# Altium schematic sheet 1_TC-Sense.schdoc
size 307 x 218 mm; Symbol: Drawing-Symbol_A4; Device: Drawing-Symbol_A4; @Project Name: Temp_Con_V116; @Page Count: 2; @Update Date: 2025-01-28; @Create Date: 2025-01-28; @Schematic Name: TC_485; @Page No: 1; @Page Name: TC-Sense; Company: EasyEDA.com; Version: V1.0; Page Size: A4; @Create Time: 02:07:35; @Update Time: 11:24:21; Width: 1170; Height: 825; Region Start: 1; X Region Count: 6; Y Region Count: 4; Blade Width: 10; Title Block Position: 3; @Board Name: TEMP_TC_485
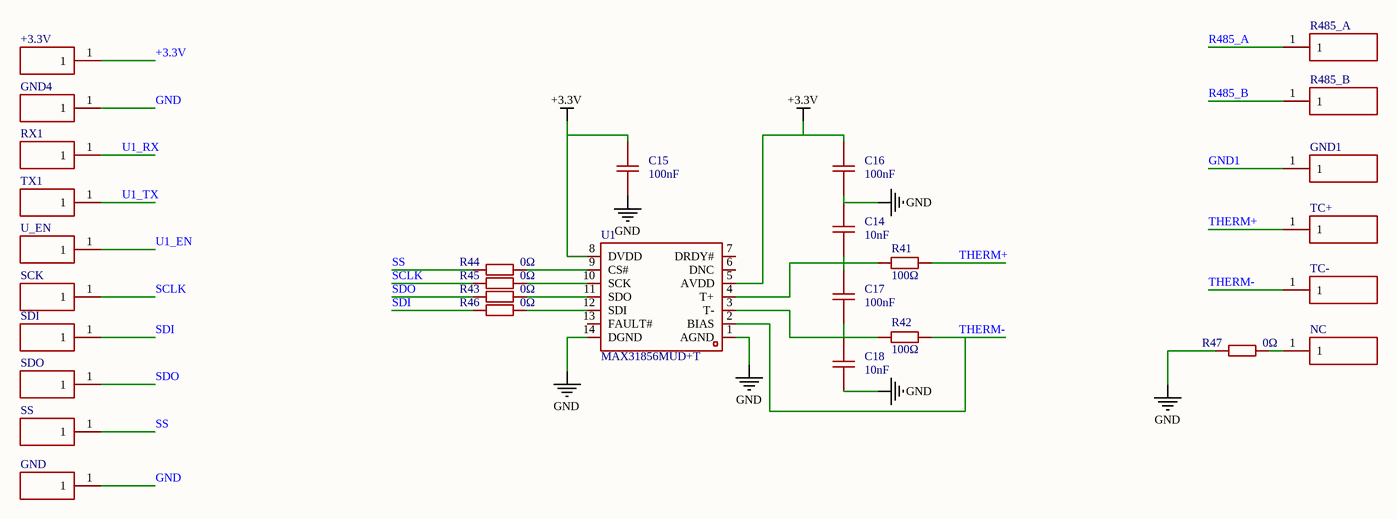
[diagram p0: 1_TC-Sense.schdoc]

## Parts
+3.3V  (no value)  [S_FT]
C14  10nF  [C0805]
C15  100nF  [C0805]
C16  100nF  [C0805]
C17  100nF  [C0805]
C18  10nF  [C0805]
GND  (no value)  [S_FT]
GND1  (no value)  [B_FT]
GND4  (no value)  [S_FT]
NC  (no value)  [B_FT]
R41  100Ω  [R0805]
R42  100Ω  [R0805]
R43  0Ω  [R0805]
R44  0Ω  [R0805]
R45  0Ω  [R0805]
R46  0Ω  [R0805]
R47  0Ω  [R0805]
R485_A  (no value)  [B_FT]
R485_B  (no value)  [B_FT]
RX1  (no value)  [S_FT]
SCK  (no value)  [S_FT]
SDI  (no value)  [S_FT]
SDO  (no value)  [S_FT]
SS  (no value)  [S_FT]
TC+  (no value)  [B_FT]
TC-  (no value)  [B_FT]
TX1  (no value)  [S_FT]
U1  MAX31856MUD+T  [TSSOP-14_L5.0-W4.4-P0.65-LS6.4-BL]
U_EN  (no value)  [S_FT]

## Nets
+3.3V: +3.3V.1 C15.1 C16.1 U1.5(AVDD) U1.8(DVDD)
GND: C14.1 C15.2 C16.2 C18.1 GND.1 GND4.1 R47.1 U1.1(AGND) U1.14(DGND)
GND1: GND1.1
R485_A: R485_A.1
R485_B: R485_B.1
SCLK: R45.1 SCK.1
SDI: R46.1 SDI.1
SDO: R43.1 SDO.1
SS: R44.1 SS.1
THERM+: R41.2 TC+.1
THERM-: R42.2 TC-.1 U1.2(BIAS)
U1_EN: U_EN.1
U1_RX: RX1.1
U1_TX: TX1.1
NetC14_2: C14.2 C17.1 R41.1 U1.4(T+)
NetC17_2: C17.2 C18.2 R42.1 U1.3(T-)
NetNC_1: NC.1 R47.2
NetR43_2: R43.2 U1.11(SDO)
NetR44_2: R44.2 U1.9(CS#)
NetR45_2: R45.2 U1.10(SCK)
NetR46_2: R46.2 U1.12(SDI)

Not connected (* = marked no-connect by the designer): U1 6(DNC) 7(DRDY#) 13(FAULT#)

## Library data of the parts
+3.3V GND GND4 RX1 SCK SDI SDO SS TX1 U_EN = S_TM: Add into BOM: no
C14 C18 = CC0805KRX7R9BB103: Manufacturer: YAGEO(国巨); Add into BOM: yes; Tolerance: ±10%
C15-C17 = CC0805KRX7R9BB104: Manufacturer: YAGEO(国巨); Add into BOM: yes; Tolerance: ±10%
GND1 NC R485_A R485_B TC+ TC- = B_TM: Add into BOM: no
R41 R42 = RC0805FR-07100RL: Manufacturer: YAGEO(国巨); Add into BOM: yes; Tolerance: ±1%; Temperature Coefficient: ±100ppm/℃
R43-R46 = RC0805JR-070RL: Manufacturer: YAGEO(国巨); Add into BOM: yes; Tolerance: ±5%
R47 = RC0805JR-070RL: Manufacturer: YAGEO(国巨); Add into BOM: no; Convert to PCB: yes; Tolerance: ±5%
U1 = MAX31856MUD+T: Manufacturer: ADI(亚德诺)/MAXIM(美信); Add into BOM: yes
